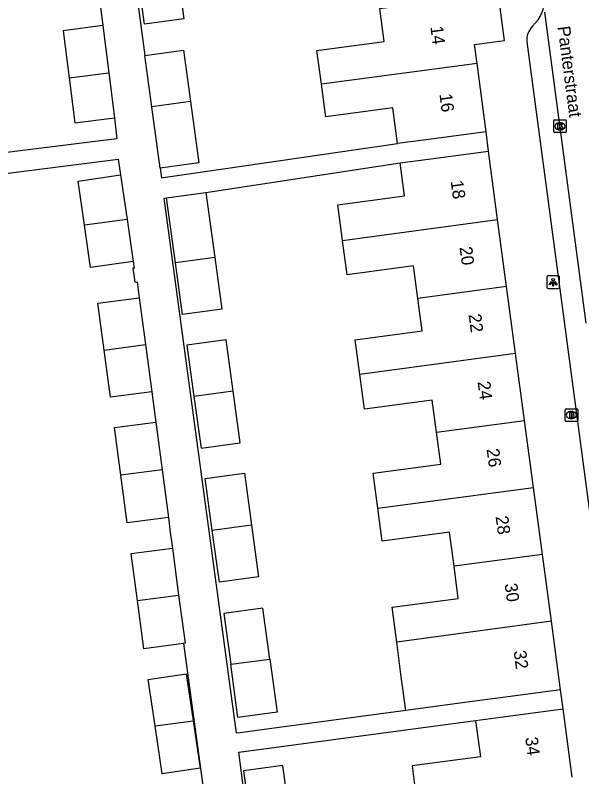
# Model space of a CAD drawing. Extents: x 163150 to 163546, y 380933 to 381635.
# Drawn here: x 163356 to 163400.8, y 381373.6 to 381434 of the extents above; entities that cross this region are included whole.
import ezdxf

# ---------------------------------------------------------------- set-up
doc = ezdxf.new("R2010")
doc.units = 0
for name, color, linetype in [('IMGEO_Brandkraan', 7, 'Continuous'), ('IMGEO_Kolk', 7, 'Continuous'), ('IMGEO_Lichtpunt', 7, 'Continuous'), ('IMGEO_Openbare_ruimte_label', 7, 'Continuous'), ('IMGEO_Pand', 7, 'Continuous'), ('IMGEO_Pand_nummerreeks', 7, 'Continuous'), ('IMGEO_Rijbaan_lokaal_open', 7, 'Continuous'), ('IMGEO_Voetpad_open', 7, 'Continuous')]:
    doc.layers.add(name, color=color, linetype=linetype)

msp = doc.modelspace()

# ---------------------------------------------------------------- linework, layer by layer
at = {"layer": 'IMGEO_Brandkraan'}
for p, q in [((163399.52, 381401.841), (163399.52, 381402.693)), ((163399.595, 381402.767), (163400.447, 381402.767)), ((163400.521, 381402.693), (163400.521, 381401.841)), ((163400.008, 381402.547), (163400.033, 381402.547)), ((163400.447, 381401.767), (163399.595, 381401.767)), ((163400.031, 381401.987), (163400.006, 381401.987))]:
    msp.add_line(p, q, dxfattribs=at)
for points in [[(163399.52, 381401.841), (163399.52, 381402.693)], [(163399.595, 381402.767), (163400.447, 381402.767)], [(163400.521, 381402.693), (163400.521, 381401.841)], [(163399.868, 381402.467), (163399.868, 381402.067), (163400.081, 381402.067)], [(163400.099, 381402.467), (163399.868, 381402.467)], [(163400.047, 381402.386), (163399.993, 381402.386), (163399.993, 381402.31)], [(163399.993, 381402.31), (163400.046, 381402.31)], [(163400.055, 381402.234), (163399.993, 381402.234), (163399.993, 381402.153)], [(163399.993, 381402.153), (163400.055, 381402.153)], [(163400.447, 381401.767), (163399.595, 381401.767)]]:
    msp.add_lwpolyline(points, dxfattribs=at)
for centre, radius, start, end in [((163399.597, 381402.691), 0.0765, 91.55205, 178.44795), ((163399.597, 381402.691), 0.0765, 91.55205, 178.44795), ((163400.445, 381402.691), 0.0765, 1.55205, 88.44795), ((163400.445, 381402.691), 0.0765, 1.55205, 88.44795), ((163400.048, 381402.348), 0.0379, 267.82845, 90.93552), ((163400.056, 381402.193), 0.0404, 269.87594, 90.50774), ((163400.087, 381402.318), 0.251, 268.66757, 293.53466), ((163400.103, 381402.322), 0.145, 59.4692, 91.53667), ((163400.128, 381402.369), 0.0922, 285.51372, 58.15012), ((163400.133, 381402.177), 0.105, 301.31148, 78.98903), ((163399.597, 381401.843), 0.0765, 181.55205, 268.44795), ((163399.597, 381401.843), 0.0765, 181.55205, 268.44795), ((163400.445, 381401.843), 0.0765, 271.55205, 358.44795), ((163400.445, 381401.843), 0.0765, 271.55205, 358.44795)]:
    msp.add_arc(centre, radius, start, end, dxfattribs=at)
for centre, major_axis, ratio, start_param, end_param in [((163400.007, 381402.267), (-0.387, 0.002), 0.722429, 4.712389, 7.853982), ((163400.032, 381402.267), (-0.39, 0.002), 0.717154, 1.570796, 4.712389)]:
    msp.add_ellipse(centre, major_axis=major_axis, ratio=ratio, start_param=start_param, end_param=end_param, dxfattribs=at)
at = {"layer": 'IMGEO_Kolk'}
for p, q in [((163398.693, 381425.658), (163399.545, 381425.658)), ((163398.618, 381424.732), (163398.618, 381425.584)), ((163399.106, 381425.438), (163399.131, 381425.438)), ((163399.619, 381425.584), (163399.619, 381424.732)), ((163399.545, 381424.658), (163398.693, 381424.658)), ((163399.129, 381424.878), (163399.104, 381424.878))]:
    msp.add_line(p, q, dxfattribs=at)
for points in [[(163398.693, 381425.658), (163399.545, 381425.658)], [(163398.618, 381424.732), (163398.618, 381425.584)], [(163398.939, 381425.358), (163399.062, 381425.358), (163399.062, 381425.207), (163399.192, 381425.358), (163399.356, 381425.358), (163399.21, 381425.207), (163399.363, 381424.958), (163399.211, 381424.958), (163399.126, 381425.122), (163399.062, 381425.055), (163399.062, 381424.958), (163398.939, 381424.958), (163398.939, 381425.358)], [(163399.619, 381425.584), (163399.619, 381424.732)], [(163399.545, 381424.658), (163398.693, 381424.658)]]:
    msp.add_lwpolyline(points, dxfattribs=at)
for centre, start, end in [((163398.695, 381425.582), 91.55205, 178.44795), ((163398.695, 381425.582), 91.55205, 178.44795), ((163399.543, 381425.582), 1.55205, 88.44795), ((163399.543, 381425.582), 1.55205, 88.44795), ((163398.695, 381424.734), 181.55205, 268.44795), ((163398.695, 381424.734), 181.55205, 268.44795), ((163399.543, 381424.734), 271.55205, 358.44795), ((163399.543, 381424.734), 271.55205, 358.44795)]:
    msp.add_arc(centre, 0.0765, start, end, dxfattribs=at)
for centre, major_axis, ratio, start_param, end_param in [((163399.105, 381425.158), (-0.387, 0.002), 0.722429, 4.712389, 7.853982), ((163399.13, 381425.158), (-0.39, 0.002), 0.717154, 1.570796, 4.712389)]:
    msp.add_ellipse(centre, major_axis=major_axis, ratio=ratio, start_param=start_param, end_param=end_param, dxfattribs=at)
at = {"layer": 'IMGEO_Lichtpunt'}
for p, q in [((163398.076, 381413.202), (163398.076, 381412.395)), ((163398.076, 381413.202), (163398.076, 381412.395)), ((163398.978, 381413.297), (163398.17, 381413.297)), ((163398.978, 381413.297), (163398.17, 381413.297)), ((163399.072, 381412.395), (163399.072, 381413.202)), ((163399.072, 381412.395), (163399.072, 381413.202)), ((163398.17, 381412.301), (163398.978, 381412.301)), ((163398.17, 381412.301), (163398.978, 381412.301))]:
    msp.add_line(p, q, dxfattribs=at)
for points in [[(163398.45, 381412.866), (163398.489, 381412.838), (163398.301, 381412.576), (163398.263, 381412.603), (163398.45, 381412.866)], [(163398.552, 381412.818), (163398.599, 381412.818), (163398.599, 381412.496), (163398.552, 381412.496), (163398.552, 381412.818)], [(163398.662, 381412.838), (163398.7, 381412.865), (163398.887, 381412.603), (163398.848, 381412.575), (163398.662, 381412.838)]]:
    msp.add_lwpolyline(points, dxfattribs=at)
msp.add_circle((163398.575, 381413), 0.0994, dxfattribs=at)
for centre, start, end in [((163398.17, 381413.202), 90, 180), ((163398.17, 381413.202), 90, 180), ((163398.978, 381413.202), 0, 90), ((163398.978, 381413.202), 0, 90), ((163398.17, 381412.395), 180, 270), ((163398.17, 381412.395), 180, 270), ((163398.978, 381412.395), 270, 0), ((163398.978, 381412.395), 270, 360)]:
    msp.add_arc(centre, 0.0946, start, end, dxfattribs=at)
at = {"layer": 'IMGEO_Pand'}
for points in [[(163368.76, 381437.746), (163369.318, 381433.676), (163366.211, 381433.263), (163365.653, 381437.332)], [(163392.548, 381430.137), (163392.348, 381431.631), (163394.726, 381431.949), (163394.218, 381435.749)], [(163380.218, 381428.496), (163379.861, 381431.163), (163385.189, 381431.876), (163384.839, 381434.5), (163386.821, 381434.764)], [(163362.911, 381433.135), (163359.774, 381432.718), (163360.238, 381429.01)], [(163362.911, 381433.135), (163363.378, 381429.402)], [(163366.229, 381430.763), (163369.3, 381431.185), (163369.857, 381427.123)], [(163366.786, 381426.701), (163366.229, 381430.763)], [(163392.548, 381430.137), (163380.218, 381428.496)], [(163393.271, 381424.727), (163392.548, 381430.137)], [(163360.238, 381429.01), (163363.378, 381429.402)], [(163363.378, 381429.402), (163363.825, 381425.828)], [(163360.238, 381429.01), (163360.685, 381425.436), (163363.825, 381425.828)], [(163386.258, 381423.789), (163385.88, 381426.614), (163380.565, 381425.903), (163380.218, 381428.496)], [(163369.857, 381427.123), (163366.786, 381426.701)], [(163369.857, 381427.123), (163370.524, 381422.269), (163367.452, 381421.847)], [(163367.452, 381421.847), (163366.786, 381426.701)], [(163393.271, 381424.727), (163388.316, 381424.064), (163386.258, 381423.789)], [(163386.457, 381422.253), (163388.494, 381422.525), (163393.449, 381423.188)], [(163394.174, 381417.763), (163393.449, 381423.188)], [(163381.891, 381416.116), (163381.515, 381418.931), (163386.807, 381419.639), (163386.457, 381422.253)], [(163361.457, 381417.324), (163360.95, 381420.808), (163364.321, 381421.299)], [(163364.321, 381421.299), (163364.836, 381417.763)], [(163367.965, 381419.491), (163371.07, 381419.917)], [(163371.07, 381419.917), (163371.777, 381414.76)], [(163368.671, 381414.343), (163367.965, 381419.491)], [(163364.836, 381417.763), (163361.457, 381417.324)], [(163364.836, 381417.763), (163365.319, 381414.45)], [(163381.891, 381416.116), (163394.174, 381417.763)], [(163394.884, 381412.456), (163394.174, 381417.763)], [(163365.319, 381414.45), (163361.948, 381413.958), (163361.457, 381417.324)], [(163387.868, 381411.515), (163387.523, 381414.094), (163382.256, 381413.39), (163381.891, 381416.116)], [(163371.777, 381414.76), (163372.339, 381410.664), (163369.233, 381410.248), (163368.671, 381414.343)], [(163371.777, 381414.76), (163368.671, 381414.343)], [(163394.884, 381412.456), (163387.868, 381411.515)], [(163395.594, 381407.147), (163394.884, 381412.456)], [(163363.017, 381407.423), (163362.526, 381411.139), (163365.794, 381411.571)], [(163365.794, 381411.571), (163366.287, 381407.849)], [(163383.26, 381405.492), (163382.893, 381408.24), (163388.211, 381408.951), (163387.868, 381411.515)], [(163373.233, 381404.147), (163372.674, 381408.225), (163369.568, 381407.808), (163370.127, 381403.73)], [(163363.017, 381407.423), (163366.287, 381407.849)], [(163366.287, 381407.849), (163366.781, 381404.116)], [(163366.781, 381404.116), (163363.512, 381403.691), (163363.017, 381407.423)], [(163395.594, 381407.147), (163383.26, 381405.492)], [(163396.304, 381401.84), (163395.594, 381407.147)], [(163389.332, 381400.905), (163388.991, 381403.458), (163383.628, 381402.741), (163383.26, 381405.492)], [(163373.233, 381404.147), (163370.127, 381403.73)], [(163370.127, 381403.73), (163370.688, 381399.638), (163373.794, 381400.055), (163373.233, 381404.147)], [(163364.332, 381397.494), (163363.831, 381401.281), (163367.1, 381401.706)], [(163367.1, 381401.706), (163367.601, 381397.919)], [(163389.332, 381400.905), (163396.304, 381401.84)], [(163397.014, 381396.532), (163396.304, 381401.84)], [(163384.683, 381394.878), (163384.311, 381397.662), (163389.67, 381398.378), (163389.332, 381400.905)], [(163367.601, 381397.919), (163364.332, 381397.494)], [(163367.601, 381397.919), (163368.1, 381394.146)], [(163368.1, 381394.146), (163364.831, 381393.72), (163364.332, 381397.494)], [(163371.582, 381393.121), (163371.018, 381397.232), (163374.124, 381397.649), (163374.688, 381393.537)], [(163384.683, 381394.878), (163397.014, 381396.532)], [(163397.724, 381391.224), (163397.014, 381396.532)], [(163390.725, 381390.285), (163390.365, 381392.974), (163385.033, 381392.26), (163384.683, 381394.878)], [(163374.688, 381393.537), (163375.249, 381389.445), (163372.144, 381389.028), (163371.582, 381393.121)], [(163374.688, 381393.537), (163371.582, 381393.121)], [(163365.646, 381387.562), (163365.153, 381391.29), (163368.422, 381391.716)], [(163368.422, 381391.716), (163368.916, 381387.987)], [(163397.724, 381391.224), (163390.725, 381390.285)], [(163398.433, 381385.916), (163397.724, 381391.224)], [(163386.184, 381384.272), (163385.815, 381387.032), (163391.066, 381387.735), (163390.725, 381390.285)], [(163365.646, 381387.562), (163368.916, 381387.987)], [(163369.306, 381384.164), (163366.151, 381383.746), (163365.646, 381387.562)], [(163368.916, 381387.987), (163369.42, 381384.179), (163369.306, 381384.164)], [(163376.144, 381382.924), (163375.589, 381386.966), (163372.484, 381386.549), (163373.038, 381382.508)], [(163398.433, 381385.916), (163386.184, 381384.272)], [(163399.159, 381380.49), (163398.433, 381385.916)], [(163386.909, 381378.852), (163386.523, 381381.737), (163386.184, 381384.272)], [(163373.038, 381382.508), (163376.144, 381382.924)], [(163376.144, 381382.924), (163376.722, 381378.71), (163373.617, 381378.284), (163373.038, 381382.508)], [(163367.05, 381377.641), (163366.503, 381381.299), (163369.503, 381381.747), (163370.059, 381378.032)], [(163399.159, 381380.49), (163394.204, 381379.827), (163392.162, 381379.554), (163386.909, 381378.852)], [(163392.431, 381378.067), (163394.407, 381378.327), (163399.364, 381378.978)], [(163400.076, 381373.565), (163399.364, 381378.978)], [(163370.059, 381378.032), (163370.62, 381374.281), (163367.62, 381373.832), (163367.05, 381377.641)], [(163367.05, 381377.641), (163370.059, 381378.032)], [(163392.431, 381378.067), (163392.812, 381375.166), (163387.405, 381374.455), (163387.736, 381371.936)], [(163377.694, 381370.61), (163377.161, 381374.494), (163374.056, 381374.068), (163374.587, 381370.2)]]:
    msp.add_lwpolyline(points, dxfattribs=at)
at = {"layer": 'IMGEO_Rijbaan_lokaal_open'}
msp.add_lwpolyline([(163401.195, 381409.545), (163397.929, 381434.214)], dxfattribs=at)
at = {"layer": 'IMGEO_Voetpad_open'}
for points in [[(163380.504, 381466.365), (163365.152, 381464.049), (163362.047, 381463.623), (163361.868, 381463.599), (163366.229, 381430.763)], [(163362.56, 381435.613), (163362.755, 381434.384), (163362.911, 381433.135)], [(163397.386, 381433.589), (163396.927, 381433.071)], [(163396.502, 381431.854), (163404.026, 381375.407)], [(163363.825, 381425.828), (163364.034, 381424.153), (163345.271, 381421.825)], [(163393.449, 381423.188), (163393.271, 381424.727)], [(163367.452, 381421.847), (163367.56, 381421.064), (163367.878, 381421.111), (163370.98, 381421.563), (163386.258, 381423.789)], [(163345.444, 381420.177), (163364.137, 381422.557), (163364.321, 381421.299)], [(163371.07, 381419.917), (163386.457, 381422.253)], [(163386.909, 381378.852), (163376.889, 381377.496), (163373.783, 381377.077), (163373.493, 381377.038), (163367.775, 381419.465), (163367.965, 381419.491)], [(163365.319, 381414.45), (163365.397, 381413.911), (163365.299, 381413.897), (163365.447, 381412.799), (163365.628, 381412.823), (163365.794, 381411.571)], [(163366.781, 381404.116), (163366.944, 381402.883), (163367.1, 381401.706)], [(163368.1, 381394.146), (163368.258, 381392.954), (163368.422, 381391.716)], [(163369.306, 381384.164), (163370.799, 381373.082), (163370.824, 381372.885), (163352.109, 381370.526)], [(163399.364, 381378.978), (163399.159, 381380.49)], [(163399.932, 381335.719), (163382.784, 381333.502), (163379.676, 381333.1), (163379.182, 381333.036), (163373.686, 381375.541), (163392.431, 381378.067)]]:
    msp.add_lwpolyline(points, dxfattribs=at)
for centre, radius, start, end in [((163394.354, 381435.528), 3.599, 327.39184, 347.0674), ((163397.991, 381432.017), 1.498, 135.25685, 186.24277)]:
    msp.add_arc(centre, radius, start, end, dxfattribs=at)

# ---------------------------------------------------------------- texts
at = {"layer": 'IMGEO_Openbare_ruimte_label'}
msp.add_text('Panterstraat', height=1, rotation=277.47342, dxfattribs=at).set_placement((163398.922, 381433.043))
at = {"layer": 'IMGEO_Pand_nummerreeks'}
for s, rotation, p in [('14', 277.6144, (163388.849, 381433.05)), ('16', 277.61476, (163389.565, 381427.697)), ('18', 277.61697, (163390.457, 381420.81)), ('20', 277.61697, (163391.159, 381415.563)), ('22', 277.61697, (163391.872, 381410.231)), ('24', 277.61697, (163392.587, 381404.891)), ('26', 277.61697, (163393.3, 381399.554)), ('28', 277.61697, (163394.014, 381394.214)), ('30', 277.61697, (163394.728, 381388.876)), ('32', 277.6144, (163395.441, 381383.546)), ('34', 277.4914, (163396.357, 381376.692))]:
    msp.add_text(s, height=1, rotation=rotation, dxfattribs=at).set_placement(p)

doc.saveas('drawing.dxf')
